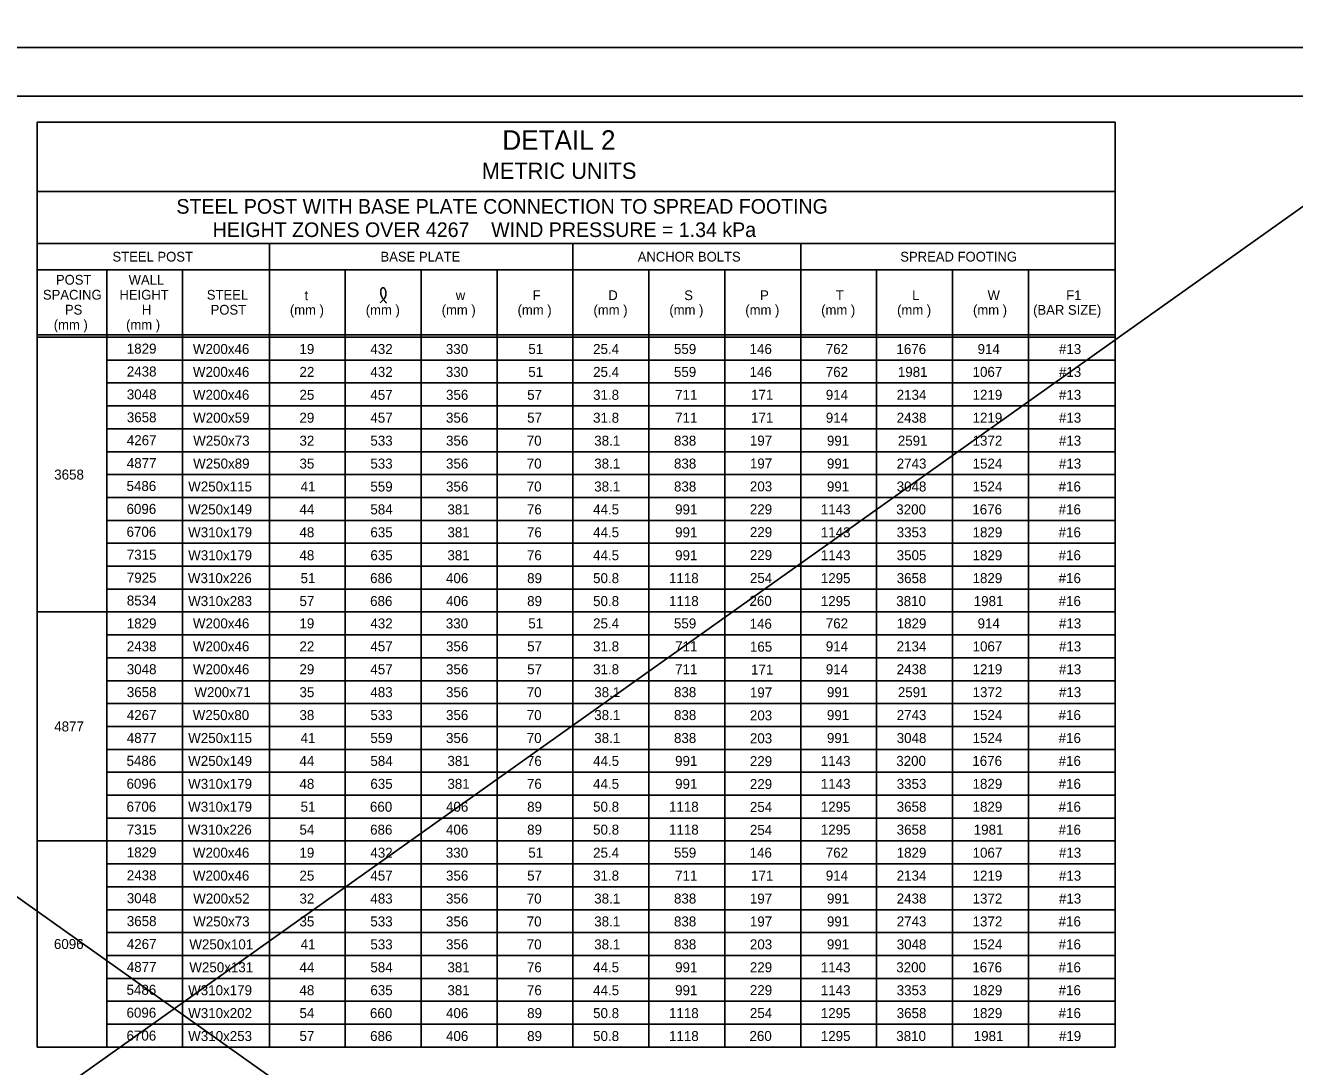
# Model space of a CAD drawing. Extents: x 3475 to 6558, y -3780 to 1166.
# Drawn here: x 5826.3 to 6216.5, y -929.6 to -609.5 of the extents above; entities that cross this region are included whole.
import ezdxf

# ---------------------------------------------------------------- set-up
doc = ezdxf.new("R2010")
doc.units = 0
for name, color, linetype in [('1', 7, 'Continuous'), ('2', 7, 'Continuous'), ('PLT-BNDY', 7, 'Continuous')]:
    doc.layers.add(name, color=color, linetype=linetype)

msp = doc.modelspace()

# ---------------------------------------------------------------- linework, layer by layer
at = {"layer": '1'}
for p, q in [((6267.74, -630.59), (5473.63, -1194.98)), ((5475.9, -630.59), (6271.14, -1194.98)), ((5830.01, -639.3), (5830.01, -923.63)), ((6161.34, -639.3), (5830.01, -639.3)), ((6161.34, -639.3), (6161.34, -923.63)), ((6161.34, -660.64), (5830.01, -660.64)), ((5830.01, -676.64), (6161.34, -676.64)), ((5901.34, -676.64), (5901.34, -923.63)), ((5994.67, -676.64), (5994.67, -923.63)), ((6064.68, -676.64), (6064.68, -923.63)), ((5830.01, -684.64), (6161.34, -684.64)), ((5830.01, -684.64), (5898.01, -684.64)), ((5830.01, -684.64), (5898.01, -684.64)), ((5830.01, -684.64), (5898.01, -684.64)), ((5830.01, -684.64), (5898.01, -684.64)), ((5851.34, -923.63), (5851.34, -684.64)), ((5874.67, -684.64), (5874.67, -923.63)), ((5924.67, -684.64), (5924.67, -923.63)), ((5948.01, -684.64), (5948.01, -923.63)), ((5971.34, -684.64), (5971.34, -923.63)), ((6018.01, -684.64), (6018.01, -923.63)), ((6041.34, -684.64), (6041.34, -923.63)), ((6088.01, -684.64), (6088.01, -923.63)), ((6111.34, -684.64), (6111.34, -923.63)), ((6134.68, -684.64), (6134.68, -923.63)), ((5830.01, -704.64), (6161.34, -704.64)), ((5830.01, -705.39), (6161.34, -705.39)), ((5851.34, -712.43), (6161.34, -712.43)), ((5851.34, -719.47), (6161.34, -719.47)), ((5851.34, -726.51), (6161.34, -726.51)), ((5851.34, -733.55), (6161.34, -733.55)), ((5851.34, -740.59), (6161.34, -740.59)), ((5851.34, -747.63), (6161.34, -747.63)), ((5851.34, -754.67), (6161.34, -754.67)), ((5851.34, -761.71), (6161.34, -761.71)), ((5851.34, -768.75), (6161.34, -768.75)), ((5851.34, -775.79), (6161.34, -775.79)), ((5851.34, -782.83), (6161.34, -782.83)), ((5830.01, -789.87), (6161.34, -789.87)), ((5851.34, -796.91), (6161.34, -796.91)), ((5851.34, -803.95), (6161.34, -803.95)), ((5851.34, -810.99), (6161.34, -810.99)), ((5851.34, -818.03), (6161.34, -818.03)), ((5851.34, -825.07), (6161.34, -825.07)), ((5851.34, -832.11), (6161.34, -832.11)), ((5851.34, -839.15), (6161.34, -839.15)), ((5851.34, -846.19), (6161.34, -846.19)), ((5851.34, -853.23), (6161.34, -853.23)), ((5830.01, -860.27), (6161.34, -860.27)), ((5830.01, -860.27), (6161.34, -860.27)), ((5851.34, -867.31), (6161.34, -867.31)), ((5851.34, -874.35), (6161.34, -874.35)), ((5851.34, -881.39), (6161.34, -881.39)), ((5851.34, -888.43), (6161.34, -888.43)), ((5851.34, -895.47), (6161.34, -895.47)), ((5851.34, -902.51), (6161.34, -902.51)), ((5851.34, -909.55), (6161.34, -909.55)), ((5851.34, -916.59), (6161.34, -916.59)), ((5830.01, -923.63), (6161.34, -923.63))]:
    msp.add_line(p, q, dxfattribs=at)
msp.add_spline([(5935.4, -694.81), (5935.6, -694.64), (5935.73, -694.51), (5935.93, -694.31), (5936.09, -694.14), (5936.37, -693.94), (5936.56, -693.68), (5936.74, -693.49), (5936.86, -693.26), (5936.97, -693), (5937.05, -692.77), (5937.13, -692.54), (5937.15, -692.35), (5937.19, -692.1), (5937.2, -691.88), (5937.19, -691.63), (5937.14, -691.38), (5937.09, -691.14), (5937.03, -690.91), (5936.95, -690.68), (5936.87, -690.54), (5936.78, -690.44), (5936.68, -690.35), (5936.59, -690.26), (5936.47, -690.2), (5936.39, -690.18), (5936.22, -690.18), (5936.13, -690.2), (5935.98, -690.26), (5935.88, -690.34), (5935.82, -690.42), (5935.76, -690.54), (5935.69, -690.66), (5935.65, -690.8), (5935.61, -690.91), (5935.58, -691.15), (5935.55, -691.32), (5935.58, -691.51), (5935.58, -691.71), (5935.61, -691.98), (5935.64, -692.22), (5935.67, -692.38), (5935.75, -692.6), (5935.85, -692.83), (5935.94, -693.03), (5936.04, -693.22), (5936.16, -693.45), (5936.35, -693.63), (5936.47, -693.84), (5936.61, -694), (5936.72, -694.18), (5936.86, -694.35), (5936.99, -694.52), (5937.1, -694.63), (5937.21, -694.76), (5937.32, -694.93)], degree=3, dxfattribs=at)
at = {"layer": '2'}
msp.add_line((5483.34, -631.31), (6269.34, -631.31), dxfattribs=at)
at = {"layer": 'PLT-BNDY'}
for points in [[(5443.34, -22.31), (6284.34, -22.31), (6284.34, -616.31), (5443.34, -616.31)], [(5443.34, -616.31), (6284.34, -616.31), (6284.34, -1210.31), (5443.34, -1210.31)]]:
    msp.add_lwpolyline(points, close=True, dxfattribs=at)

# ---------------------------------------------------------------- texts
at = {"layer": '1'}
for s, height, p in [('DETAIL 2', 6, (5972.97, -647.79)), ('METRIC UNITS', 5.0001, (5966.64, -656.74)), ('STEEL POST WITH BASE PLATE CONNECTION TO SPREAD FOOTING', 4.5001, (5872.77, -667.43)), ('HEIGHT ZONES OVER 4267    WIND PRESSURE = 1.34 kPa', 4.5001, (5883.93, -674.6)), ('STEEL POST', 3, (5853.11, -682.14)), ('BASE PLATE', 3, (5935.51, -682.14)), ('ANCHOR BOLTS', 3, (6014.58, -682.14)), ('SPREAD FOOTING', 3, (6095.3, -682.14)), ('POST', 3, (5835.73, -689.24)), ('WALL', 3, (5858.09, -689.24)), ('SPACING', 3, (5831.73, -693.84)), ('HEIGHT', 3, (5855.26, -693.84)), ('STEEL', 3, (5882.11, -693.86)), ('t', 3, (5912.17, -694)), ('w', 3, (5958.65, -694)), ('F', 3, (5982.26, -694)), ('D', 3, (6005.54, -694)), ('S', 3, (6028.88, -694)), ('P', 3, (6052.2, -694)), ('T', 3, (6075.49, -694)), ('L', 3, (6098.94, -694)), ('W', 3, (6122.14, -694)), ('F1', 3, (6146.31, -694)), ('PS', 3, (5838.49, -698.44)), ('H', 3, (5862.14, -698.44)), ('POST', 3, (5883.28, -698.46)), ('(mm )', 3, (5907.65, -698.5)), ('(mm )', 3, (5930.98, -698.5)), ('(mm )', 3, (5954.31, -698.5)), ('(mm )', 3, (5977.65, -698.5)), ('(mm )', 3, (6000.98, -698.5)), ('(mm )', 3, (6024.31, -698.5)), ('(mm )', 3, (6047.65, -698.5)), ('(mm )', 3, (6070.98, -698.5)), ('(mm )', 3, (6094.32, -698.5)), ('(mm )', 3, (6117.65, -698.5)), ('(BAR SIZE)', 3, (6136.14, -698.5)), ('(mm )', 3, (5835.06, -703.04)), ('(mm )', 3, (5857.29, -703.04)), ('1829', 3.07, (5857.51, -710.44)), ('W200x46', 3.07, (5877.84, -710.56)), ('19', 3.07, (5910.59, -710.56)), ('432', 3.07, (5932.4, -710.56)), ('330', 3.07, (5955.6, -710.56)), ('51', 3.07, (5980.95, -710.56)), ('25.4', 3.07, (6000.87, -710.56)), ('559', 3.07, (6025.72, -710.56)), ('146', 3.07, (6048.98, -710.55)), ('762', 3.07, (6072.4, -710.56)), ('1676', 3.07, (6094.12, -710.56)), ('914', 3.07, (6119.07, -710.56)), ('#13', 3.07, (6144.07, -710.56)), ('2438', 3.07, (5857.52, -717.48)), ('W200x46', 3.07, (5877.84, -717.6)), ('22', 3.07, (5910.6, -717.6)), ('432', 3.07, (5932.4, -717.6)), ('330', 3.07, (5955.6, -717.6)), ('51', 3.07, (5980.95, -717.6)), ('25.4', 3.07, (6000.87, -717.6)), ('559', 3.07, (6025.72, -717.6)), ('146', 3.07, (6048.98, -717.59)), ('762', 3.07, (6072.4, -717.6)), ('1981', 3.07, (6094.55, -717.6)), ('1067', 3.07, (6117.53, -717.6)), ('#13', 3.07, (6144.07, -717.6)), ('3048', 3.07, (5857.52, -724.52)), ('W200x46', 3.07, (5877.84, -724.65)), ('25', 3.07, (5910.6, -724.65)), ('457', 3.07, (5932.4, -724.65)), ('356', 3.07, (5955.65, -724.65)), ('57', 3.07, (5980.6, -724.65)), ('31.8', 3.07, (6000.87, -724.65)), ('711', 3.07, (6026.08, -724.65)), ('171', 3.07, (6049.42, -724.63)), ('914', 3.07, (6072.4, -724.65)), ('2134', 3.07, (6094.2, -724.65)), ('1219', 3.07, (6117.52, -724.65)), ('#13', 3.07, (6144.07, -724.65)), ('3658', 3.07, (5857.52, -731.56)), ('W200x59', 3.07, (5877.91, -731.69)), ('29', 3.07, (5910.59, -731.69)), ('457', 3.07, (5932.4, -731.69)), ('356', 3.07, (5955.65, -731.69)), ('57', 3.07, (5980.6, -731.69)), ('31.8', 3.07, (6000.87, -731.69)), ('711', 3.07, (6026.08, -731.69)), ('171', 3.07, (6049.42, -731.67)), ('914', 3.07, (6072.4, -731.69)), ('2438', 3.07, (6094.2, -731.69)), ('1219', 3.07, (6117.52, -731.69)), ('#13', 3.07, (6144.07, -731.69)), ('4267', 3.07, (5857.52, -738.6)), ('W250x73', 3.07, (5877.93, -738.74)), ('32', 3.07, (5910.6, -738.74)), ('533', 3.07, (5932.4, -738.74)), ('356', 3.07, (5955.65, -738.74)), ('70', 3.07, (5980.47, -738.74)), ('38.1', 3.07, (6001.22, -738.74)), ('838', 3.07, (6025.73, -738.74)), ('197', 3.07, (6049.07, -738.71)), ('991', 3.07, (6072.75, -738.74)), ('2591', 3.07, (6094.55, -738.74)), ('1372', 3.07, (6117.53, -738.74)), ('#13', 3.07, (6144.07, -738.74)), ('4877', 3.07, (5857.52, -745.64)), ('W250x89', 3.07, (5877.91, -745.78)), ('35', 3.07, (5910.6, -745.78)), ('533', 3.07, (5932.4, -745.78)), ('356', 3.07, (5955.65, -745.78)), ('70', 3.07, (5980.47, -745.78)), ('38.1', 3.07, (6001.22, -745.78)), ('838', 3.07, (6025.73, -745.78)), ('197', 3.07, (6049.07, -745.75)), ('991', 3.07, (6072.75, -745.78)), ('2743', 3.07, (6094.2, -745.78)), ('1524', 3.07, (6117.53, -745.78)), ('#13', 3.07, (6144.07, -745.78)), ('3658', 3.07, (5835.2, -749.16)), ('5486', 3.07, (5857.43, -752.68)), ('W250x115', 3.07, (5876.39, -752.83)), ('41', 3.07, (5910.95, -752.83)), ('559', 3.07, (5932.39, -752.83)), ('356', 3.07, (5955.65, -752.83)), ('70', 3.07, (5980.47, -752.83)), ('38.1', 3.07, (6001.22, -752.83)), ('838', 3.07, (6025.73, -752.83)), ('203', 3.07, (6049.07, -752.79)), ('991', 3.07, (6072.75, -752.83)), ('3048', 3.07, (6094.2, -752.83)), ('1524', 3.07, (6117.53, -752.83)), ('#16', 3.07, (6143.98, -752.83)), ('6096', 3.07, (5857.43, -759.72)), ('W250x149', 3.07, (5876.38, -759.87)), ('44', 3.07, (5910.6, -759.87)), ('584', 3.07, (5932.4, -759.87)), ('381', 3.07, (5956.08, -759.87)), ('76', 3.07, (5980.52, -759.87)), ('44.5', 3.07, (6000.87, -759.87)), ('991', 3.07, (6026.08, -759.87)), ('229', 3.07, (6049.06, -759.83)), ('1143', 3.07, (6070.87, -759.87)), ('3200', 3.07, (6094.07, -759.87)), ('1676', 3.07, (6117.45, -759.87)), ('#16', 3.07, (6143.98, -759.87)), ('6706', 3.07, (5857.43, -766.76)), ('W310x179', 3.07, (5876.38, -766.91)), ('48', 3.07, (5910.6, -766.91)), ('635', 3.07, (5932.4, -766.91)), ('381', 3.07, (5956.08, -766.91)), ('76', 3.07, (5980.52, -766.91)), ('44.5', 3.07, (6000.87, -766.91)), ('991', 3.07, (6026.08, -766.91)), ('229', 3.07, (6049.06, -766.87)), ('1143', 3.07, (6070.87, -766.91)), ('3353', 3.07, (6094.2, -766.91)), ('1829', 3.07, (6117.52, -766.91)), ('#16', 3.07, (6143.98, -766.91)), ('7315', 3.07, (5857.52, -773.8)), ('W310x179', 3.07, (5876.38, -773.96)), ('48', 3.07, (5910.6, -773.96)), ('635', 3.07, (5932.4, -773.96)), ('381', 3.07, (5956.08, -773.96)), ('76', 3.07, (5980.52, -773.96)), ('44.5', 3.07, (6000.87, -773.96)), ('991', 3.07, (6026.08, -773.96)), ('229', 3.07, (6049.06, -773.91)), ('1143', 3.07, (6070.87, -773.96)), ('3505', 3.07, (6094.2, -773.96)), ('1829', 3.07, (6117.52, -773.96)), ('#16', 3.07, (6143.98, -773.96)), ('7925', 3.07, (5857.52, -780.84)), ('W310x226', 3.07, (5876.31, -781)), ('51', 3.07, (5910.95, -781)), ('686', 3.07, (5932.32, -781)), ('406', 3.07, (5955.65, -781)), ('89', 3.07, (5980.59, -781)), ('50.8', 3.07, (6000.87, -781)), ('1118', 3.07, (6024.2, -781)), ('254', 3.07, (6049.07, -780.95)), ('1295', 3.07, (6070.87, -781)), ('3658', 3.07, (6094.2, -781)), ('1829', 3.07, (6117.52, -781)), ('#16', 3.07, (6143.98, -781)), ('8534', 3.07, (5857.52, -787.88)), ('W310x283', 3.07, (5876.39, -788.05)), ('57', 3.07, (5910.6, -788.05)), ('686', 3.07, (5932.32, -788.05)), ('406', 3.07, (5955.65, -788.05)), ('89', 3.07, (5980.59, -788.05)), ('50.8', 3.07, (6000.87, -788.05)), ('1118', 3.07, (6024.2, -788.05)), ('260', 3.07, (6048.94, -787.99)), ('1295', 3.07, (6070.87, -788.05)), ('3810', 3.07, (6094.07, -788.05)), ('1981', 3.07, (6117.88, -788.05)), ('#16', 3.07, (6143.98, -788.05)), ('1829', 3.07, (5857.51, -794.92)), ('W200x46', 3.07, (5877.84, -794.92)), ('19', 3.07, (5910.59, -794.92)), ('432', 3.07, (5932.4, -794.92)), ('330', 3.07, (5955.6, -794.92)), ('51', 3.07, (5980.95, -794.92)), ('25.4', 3.07, (6000.87, -794.92)), ('559', 3.07, (6025.72, -794.92)), ('146', 3.07, (6048.98, -795.03)), ('762', 3.07, (6072.4, -794.92)), ('1829', 3.07, (6094.19, -794.92)), ('914', 3.07, (6119.07, -794.92)), ('#13', 3.07, (6144.07, -794.92)), ('2438', 3.07, (5857.52, -801.96)), ('W200x46', 3.07, (5877.84, -801.97)), ('22', 3.07, (5910.6, -801.97)), ('457', 3.07, (5932.4, -801.97)), ('356', 3.07, (5955.65, -801.97)), ('57', 3.07, (5980.6, -801.97)), ('31.8', 3.07, (6000.87, -801.97)), ('711', 3.07, (6026.08, -801.97)), ('165', 3.07, (6049.07, -802.07)), ('914', 3.07, (6072.4, -801.97)), ('2134', 3.07, (6094.2, -801.97)), ('1067', 3.07, (6117.53, -801.97)), ('#13', 3.07, (6144.07, -801.97)), ('3048', 3.07, (5857.52, -809)), ('W200x46', 3.07, (5877.84, -809.01)), ('29', 3.07, (5910.59, -809.01)), ('457', 3.07, (5932.4, -809.01)), ('356', 3.07, (5955.65, -809.01)), ('57', 3.07, (5980.6, -809.01)), ('31.8', 3.07, (6000.87, -809.01)), ('711', 3.07, (6026.08, -809.01)), ('171', 3.07, (6049.42, -809.11)), ('914', 3.07, (6072.4, -809.01)), ('2438', 3.07, (6094.2, -809.01)), ('1219', 3.07, (6117.52, -809.01)), ('#13', 3.07, (6144.07, -809.01)), ('3658', 3.07, (5857.52, -816.04)), ('W200x71', 3.07, (5878.28, -816.06)), ('35', 3.07, (5910.6, -816.06)), ('483', 3.07, (5932.4, -816.06)), ('356', 3.07, (5955.65, -816.06)), ('70', 3.07, (5980.47, -816.06)), ('38.1', 3.07, (6001.22, -816.06)), ('838', 3.07, (6025.73, -816.06)), ('197', 3.07, (6049.07, -816.15)), ('991', 3.07, (6072.75, -816.06)), ('2591', 3.07, (6094.55, -816.06)), ('1372', 3.07, (6117.53, -816.06)), ('#13', 3.07, (6144.07, -816.06)), ('4267', 3.07, (5857.52, -823.08)), ('W250x80', 3.07, (5877.79, -823.1)), ('38', 3.07, (5910.6, -823.1)), ('533', 3.07, (5932.4, -823.1)), ('356', 3.07, (5955.65, -823.1)), ('70', 3.07, (5980.47, -823.1)), ('38.1', 3.07, (6001.22, -823.1)), ('838', 3.07, (6025.73, -823.1)), ('203', 3.07, (6049.07, -823.19)), ('991', 3.07, (6072.75, -823.1)), ('2743', 3.07, (6094.2, -823.1)), ('1524', 3.07, (6117.53, -823.1)), ('#16', 3.07, (6143.98, -823.1)), ('4877', 3.07, (5835.2, -826.6)), ('4877', 3.07, (5857.52, -830.12)), ('W250x115', 3.07, (5876.39, -830.15)), ('41', 3.07, (5910.95, -830.15)), ('559', 3.07, (5932.39, -830.15)), ('356', 3.07, (5955.65, -830.15)), ('70', 3.07, (5980.47, -830.15)), ('38.1', 3.07, (6001.22, -830.15)), ('838', 3.07, (6025.73, -830.15)), ('203', 3.07, (6049.07, -830.23)), ('991', 3.07, (6072.75, -830.15)), ('3048', 3.07, (6094.2, -830.15)), ('1524', 3.07, (6117.53, -830.15)), ('#16', 3.07, (6143.98, -830.15)), ('5486', 3.07, (5857.43, -837.16)), ('W250x149', 3.07, (5876.38, -837.19)), ('44', 3.07, (5910.6, -837.19)), ('584', 3.07, (5932.4, -837.19)), ('381', 3.07, (5956.08, -837.19)), ('76', 3.07, (5980.52, -837.19)), ('44.5', 3.07, (6000.87, -837.19)), ('991', 3.07, (6026.08, -837.19)), ('229', 3.07, (6049.06, -837.27)), ('1143', 3.07, (6070.87, -837.19)), ('3200', 3.07, (6094.07, -837.19)), ('1676', 3.07, (6117.45, -837.19)), ('#16', 3.07, (6143.98, -837.19)), ('6096', 3.07, (5857.43, -844.2)), ('W310x179', 3.07, (5876.38, -844.24)), ('48', 3.07, (5910.6, -844.24)), ('635', 3.07, (5932.4, -844.24)), ('381', 3.07, (5956.08, -844.24)), ('76', 3.07, (5980.52, -844.24)), ('44.5', 3.07, (6000.87, -844.24)), ('991', 3.07, (6026.08, -844.24)), ('229', 3.07, (6049.06, -844.31)), ('1143', 3.07, (6070.87, -844.24)), ('3353', 3.07, (6094.2, -844.24)), ('1829', 3.07, (6117.52, -844.24)), ('#16', 3.07, (6143.98, -844.24)), ('6706', 3.07, (5857.43, -851.24)), ('W310x179', 3.07, (5876.38, -851.28)), ('51', 3.07, (5910.95, -851.28)), ('660', 3.07, (5932.27, -851.28)), ('406', 3.07, (5955.65, -851.28)), ('89', 3.07, (5980.59, -851.28)), ('50.8', 3.07, (6000.87, -851.28)), ('1118', 3.07, (6024.2, -851.28)), ('254', 3.07, (6049.07, -851.35)), ('1295', 3.07, (6070.87, -851.28)), ('3658', 3.07, (6094.2, -851.28)), ('1829', 3.07, (6117.52, -851.28)), ('#16', 3.07, (6143.98, -851.28)), ('7315', 3.07, (5857.52, -858.28)), ('W310x226', 3.07, (5876.31, -858.32)), ('54', 3.07, (5910.6, -858.32)), ('686', 3.07, (5932.32, -858.32)), ('406', 3.07, (5955.65, -858.32)), ('89', 3.07, (5980.59, -858.32)), ('50.8', 3.07, (6000.87, -858.32)), ('1118', 3.07, (6024.2, -858.32)), ('254', 3.07, (6049.07, -858.39)), ('1295', 3.07, (6070.87, -858.32)), ('3658', 3.07, (6094.2, -858.32)), ('1981', 3.07, (6117.88, -858.32)), ('#16', 3.07, (6143.98, -858.32)), ('1829', 3.07, (5857.51, -865.32)), ('W200x46', 3.07, (5877.84, -865.41)), ('19', 3.07, (5910.59, -865.41)), ('432', 3.07, (5932.4, -865.41)), ('330', 3.07, (5955.6, -865.41)), ('25.4', 3.07, (6000.87, -865.41)), ('559', 3.07, (6025.72, -865.41)), ('146', 3.07, (6048.98, -865.43)), ('762', 3.07, (6072.4, -865.41)), ('1829', 3.07, (6094.19, -865.41)), ('1067', 3.07, (6117.53, -865.41)), ('#13', 3.07, (6144.07, -865.41)), ('51', 3.07, (5980.95, -865.41)), ('2438', 3.07, (5857.52, -872.36)), ('W200x46', 3.07, (5877.84, -872.45)), ('25', 3.07, (5910.6, -872.45)), ('457', 3.07, (5932.4, -872.45)), ('356', 3.07, (5955.65, -872.45)), ('57', 3.07, (5980.6, -872.45)), ('31.8', 3.07, (6000.87, -872.45)), ('711', 3.07, (6026.08, -872.45)), ('171', 3.07, (6049.42, -872.47)), ('914', 3.07, (6072.4, -872.45)), ('2134', 3.07, (6094.2, -872.45)), ('1219', 3.07, (6117.52, -872.45)), ('#13', 3.07, (6144.07, -872.45)), ('3048', 3.07, (5857.52, -879.4)), ('W200x52', 3.07, (5877.93, -879.5)), ('32', 3.07, (5910.6, -879.5)), ('483', 3.07, (5932.4, -879.5)), ('356', 3.07, (5955.65, -879.5)), ('70', 3.07, (5980.47, -879.5)), ('38.1', 3.07, (6001.22, -879.5)), ('838', 3.07, (6025.73, -879.5)), ('197', 3.07, (6049.07, -879.51)), ('991', 3.07, (6072.75, -879.5)), ('2438', 3.07, (6094.2, -879.5)), ('1372', 3.07, (6117.53, -879.5)), ('#13', 3.07, (6144.07, -879.5)), ('3658', 3.07, (5857.52, -886.44)), ('W250x73', 3.07, (5877.93, -886.54)), ('35', 3.07, (5910.6, -886.54)), ('533', 3.07, (5932.4, -886.54)), ('356', 3.07, (5955.65, -886.54)), ('70', 3.07, (5980.47, -886.54)), ('38.1', 3.07, (6001.22, -886.54)), ('838', 3.07, (6025.73, -886.54)), ('197', 3.07, (6049.07, -886.55)), ('991', 3.07, (6072.75, -886.54)), ('2743', 3.07, (6094.2, -886.54)), ('1372', 3.07, (6117.53, -886.54)), ('#16', 3.07, (6143.98, -886.54)), ('6096', 3.07, (5835.11, -893.48)), ('4267', 3.07, (5857.52, -893.48)), ('W250x101', 3.07, (5876.74, -893.59)), ('41', 3.07, (5910.95, -893.59)), ('533', 3.07, (5932.4, -893.59)), ('356', 3.07, (5955.65, -893.59)), ('70', 3.07, (5980.47, -893.59)), ('38.1', 3.07, (6001.22, -893.59)), ('838', 3.07, (6025.73, -893.59)), ('203', 3.07, (6049.07, -893.59)), ('991', 3.07, (6072.75, -893.59)), ('3048', 3.07, (6094.2, -893.59)), ('1524', 3.07, (6117.53, -893.59)), ('#16', 3.07, (6143.98, -893.59)), ('4877', 3.07, (5857.52, -900.52)), ('W250x131', 3.07, (5876.74, -900.63)), ('44', 3.07, (5910.6, -900.63)), ('584', 3.07, (5932.4, -900.63)), ('381', 3.07, (5956.08, -900.63)), ('76', 3.07, (5980.52, -900.63)), ('44.5', 3.07, (6000.87, -900.63)), ('991', 3.07, (6026.08, -900.63)), ('229', 3.07, (6049.06, -900.63)), ('1143', 3.07, (6070.87, -900.63)), ('3200', 3.07, (6094.07, -900.63)), ('1676', 3.07, (6117.45, -900.63)), ('#16', 3.07, (6143.98, -900.63)), ('5486', 3.07, (5857.43, -907.56)), ('W310x179', 3.07, (5876.38, -907.68)), ('48', 3.07, (5910.6, -907.68)), ('635', 3.07, (5932.4, -907.68)), ('381', 3.07, (5956.08, -907.68)), ('76', 3.07, (5980.52, -907.68)), ('44.5', 3.07, (6000.87, -907.68)), ('991', 3.07, (6026.08, -907.68)), ('229', 3.07, (6049.06, -907.67)), ('1143', 3.07, (6070.87, -907.68)), ('3353', 3.07, (6094.2, -907.68)), ('1829', 3.07, (6117.52, -907.68)), ('#16', 3.07, (6143.98, -907.68)), ('6096', 3.07, (5857.43, -914.6)), ('W310x202', 3.07, (5876.39, -914.72)), ('54', 3.07, (5910.6, -914.72)), ('660', 3.07, (5932.27, -914.72)), ('406', 3.07, (5955.65, -914.72)), ('89', 3.07, (5980.59, -914.72)), ('50.8', 3.07, (6000.87, -914.72)), ('1118', 3.07, (6024.2, -914.72)), ('254', 3.07, (6049.07, -914.71)), ('1295', 3.07, (6070.87, -914.72)), ('3658', 3.07, (6094.2, -914.72)), ('1829', 3.07, (6117.52, -914.72)), ('#16', 3.07, (6143.98, -914.72)), ('6706', 3.07, (5857.43, -921.64)), ('W310x253', 3.07, (5876.39, -921.77)), ('57', 3.07, (5910.6, -921.77)), ('686', 3.07, (5932.32, -921.77)), ('406', 3.07, (5955.65, -921.77)), ('89', 3.07, (5980.59, -921.77)), ('50.8', 3.07, (6000.87, -921.77)), ('1118', 3.07, (6024.2, -921.77)), ('260', 3.07, (6048.94, -921.75)), ('1295', 3.07, (6070.87, -921.77)), ('3810', 3.07, (6094.07, -921.77)), ('1981', 3.07, (6117.88, -921.77)), ('#19', 3.07, (6144.06, -921.77))]:
    msp.add_text(s, height=height, dxfattribs=at).set_placement(p)

doc.saveas('drawing.dxf')
